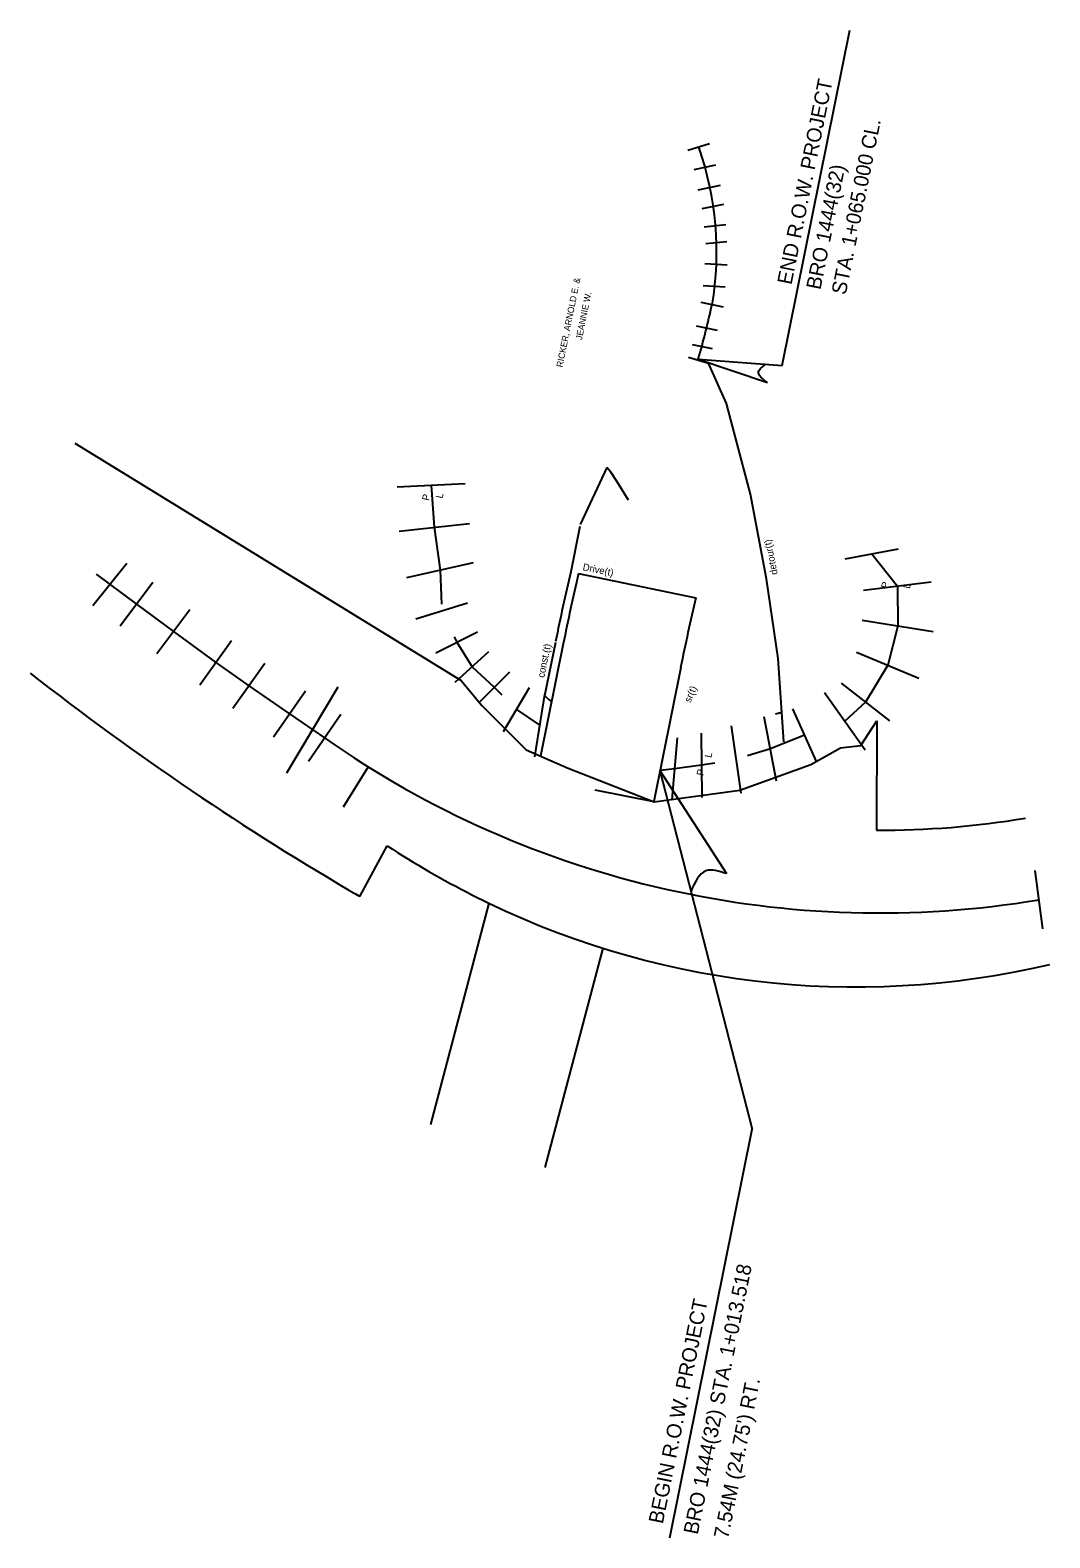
# Model space of a CAD drawing. Extents: x 516033 to 516161, y 162208 to 162397.
import ezdxf

# ---------------------------------------------------------------- set-up
doc = ezdxf.new("R2010")
doc.units = 0
for name, color, linetype in [('Level 1', 7, 'Continuous'), ('Level 10', 7, 'Continuous'), ('Level 19', 7, 'Continuous'), ('Level 3', 7, 'Continuous'), ('Level 4', 7, 'Continuous'), ('Level 6', 7, 'Continuous'), ('Level 60', 7, 'Continuous'), ('Level 7', 7, 'Continuous')]:
    doc.layers.add(name, color=color, linetype=linetype)

msp = doc.modelspace()

# ---------------------------------------------------------------- linework, layer by layer
at = {"layer": 'Level 1'}
for p, q in [((516038.43, 162344.97), (516086.83, 162315.23)), ((516101.53, 162328.62), (516116.23, 162325.59)), ((516099.62, 162319.81), (516096.79, 162305.76)), ((516099.62, 162319.81), (516099.62, 162319.81)), ((516114.33, 162316.85), (516110.95, 162300.06)), ((516086.83, 162315.23), (516089.43, 162312.09)), ((516089.43, 162312.09), (516094.97, 162306.57)), ((516136.88, 162307.11), (516138.92, 162310.2)), ((516138.92, 162310.2), (516138.87, 162296.48)), ((516094.97, 162306.57), (516100.24, 162304.24)), ((516130.62, 162304.7), (516134.35, 162306.8)), ((516134.35, 162306.8), (516136.88, 162307.11)), ((516100.24, 162304.24), (516111.01, 162300.03)), ((516121.72, 162301.49), (516130.62, 162304.7)), ((516111.01, 162300.03), (516121.72, 162301.49)), ((516074.12, 162288.2), (516077.58, 162294.54)), ((516083.04, 162259.63), (516090.36, 162287.33)), ((516097.34, 162254.25), (516104.6, 162281.71))]:
    msp.add_line(p, q, dxfattribs=at)
for centre, radius, start, end in [((516401.07, 162259.12), 307.5, 166.9373, 168.6167), ((516401.07, 162259.12), 292.5, 166.8642, 168.6167), ((516255.76, 162600.89), 361.61, 231.9427, 239.847), ((516139.23, 162407.29), 110.81, 269.8159, 279.4967), ((516137.81, 162386.45), 109.89, 236.7654, 243.1541), ((516136.26, 162382.76), 105.9, 242.9997, 283.2702)]:
    msp.add_arc(centre, radius, start, end, dxfattribs=at)
at = {"layer": 'Level 10'}
for p, q in [((516127.04, 162354.67), (516135.5, 162396.67)), ((516116.52, 162355.46), (516127.04, 162354.67)), ((516116.52, 162355.46), (516125.19, 162352.56)), ((516105.59, 162341.3), (516105.1, 162341.92)), ((516106.37, 162340.09), (516105.59, 162341.3)), ((516107.78, 162337.82), (516106.37, 162340.09)), ((516111.72, 162303.95), (516123.27, 162259.05)), ((516111.72, 162303.95), (516120.06, 162291.05)), ((516112.96, 162207.87), (516123.27, 162259.05))]:
    msp.add_line(p, q, dxfattribs=at)
for points in [[(516125.19, 162352.56), (516124.08, 162353.89), (516125, 162354.84)], [(516120.06, 162291.05), (516117.48, 162291.4), (516115.59, 162288.78)]]:
    msp.add_spline(points, degree=3, dxfattribs=at)
at = {"layer": 'Level 19'}
msp.add_arc((516137.81, 162386.45), 117.09, 236.7654, 237.0475, dxfattribs=at)
at = {"layer": 'Level 3'}
for p, q in [((516083.08, 162339.64), (516083.46, 162334.42)), ((516083.46, 162334.42), (516084.21, 162329.06)), ((516138.28, 162331.09), (516141.47, 162327.05)), ((516084.21, 162329.06), (516084.36, 162324.81)), ((516141.47, 162327.05), (516141.51, 162322.08)), ((516141.51, 162322.08), (516140.26, 162317.17)), ((516085.95, 162320.69), (516086.27, 162320.02)), ((516086.27, 162320.02), (516088.21, 162316.96)), ((516088.21, 162316.96), (516090.98, 162314.39)), ((516140.26, 162317.16), (516137.48, 162312.54)), ((516090.98, 162314.39), (516091.94, 162313.43)), ((516137.48, 162312.54), (516134.89, 162310.12)), ((516093.76, 162311.6), (516096.71, 162309.6)), ((516129.82, 162308.39), (516125.56, 162306.67)), ((516125.56, 162306.67), (516122.7, 162305.79)), ((516113.56, 162304.19), (516111.81, 162303.96)), ((516116.94, 162304.62), (516113.56, 162304.19)), ((516118.6, 162304.9), (516116.94, 162304.62))]:
    msp.add_line(p, q, dxfattribs=at)
at = {"layer": 'Level 6'}
for p, q in [((516115.24, 162381.65), (516117.95, 162382.46)), ((516116, 162379.24), (516118.73, 162379.8)), ((516116.52, 162376.69), (516119.31, 162377.26)), ((516117, 162374.33), (516119.75, 162374.89)), ((516117.29, 162372.06), (516119.98, 162372.33)), ((516117.5, 162369.95), (516120.12, 162370.21)), ((516117.34, 162367.46), (516120.15, 162367.28)), ((516117.16, 162364.69), (516119.9, 162364.51)), ((516116.86, 162362.61), (516119.64, 162362.04)), ((516116.25, 162359.66), (516118.89, 162359.12)), ((516115.77, 162357.3), (516118.28, 162356.79)), ((516115.31, 162355.7), (516117.81, 162354.96)), ((516040.71, 162324.62), (516044.97, 162329.93)), ((516041.13, 162328.55), (516046.17, 162324.8)), ((516044.12, 162322.06), (516048.22, 162327.53)), ((516046.17, 162324.8), (516050.79, 162321.36)), ((516048.73, 162318.61), (516052.85, 162324.11)), ((516050.79, 162321.36), (516056.09, 162317.49)), ((516054.1, 162314.71), (516058.08, 162320.26)), ((516056.09, 162317.49), (516060.24, 162314.58)), ((516058.22, 162311.76), (516062.26, 162317.4)), ((516060.24, 162314.58), (516065.32, 162311.07)), ((516063.32, 162308.19), (516067.32, 162313.95)), ((516071.4, 162314.4), (516064.97, 162303.61)), ((516065.32, 162311.07), (516069.71, 162308.05)), ((516067.7, 162305.15), (516071.77, 162311.01)), ((516075.18, 162304.43), (516072.04, 162299.39)), ((516159.69, 162284.12), (516158.75, 162291.45))]:
    msp.add_line(p, q, dxfattribs=at)
for centre, radius, start, end in [((516078.71, 162368.85), 40.12, 350.5878, 19.2232), ((516005.8, 162386.84), 115.1, 344.1759, 347.7005), ((516139.23, 162407.29), 121.17, 234.989, 279.4967)]:
    msp.add_arc(centre, radius, start, end, dxfattribs=at)
at = {"layer": 'Level 60'}
for p, q in [((516087.33, 162339.84), (516078.82, 162339.43)), ((516079.05, 162333.95), (516087.86, 162334.89)), ((516134.95, 162330.47), (516141.61, 162331.71)), ((516080.03, 162328.14), (516088.39, 162329.99)), ((516137.24, 162326.53), (516145.69, 162327.58)), ((516081.16, 162322.97), (516087.62, 162324.94)), ((516083.68, 162318.7), (516088.87, 162321.33)), ((516137.07, 162322.8), (516145.94, 162321.36)), ((516086.1, 162315.03), (516090.31, 162318.88)), ((516136.35, 162318.79), (516144.16, 162315.53)), ((516089.04, 162312.44), (516092.91, 162316.33)), ((516092.15, 162308.84), (516095.38, 162314.36)), ((516132.36, 162313.71), (516137.43, 162306.54)), ((516134.45, 162314.9), (516140.5, 162310.18)), ((516096.08, 162305.69), (516097.33, 162313.5)), ((516126.32, 162302.64), (516124.79, 162310.7)), ((516128.32, 162311.69), (516131.31, 162305.09)), ((516113.91, 162308.05), (516113.22, 162300.33)), ((516116.9, 162308.65), (516116.97, 162300.6)), ((516120.65, 162309.57), (516121.88, 162301.12)), ((516103.59, 162301.54), (516110.95, 162300.06))]:
    msp.add_line(p, q, dxfattribs=at)
at = {"layer": 'Level 7'}
for p, q in [((516117.83, 162354.99), (516116.53, 162355.46)), ((516105.1, 162341.92), (516101.75, 162334.76)), ((516101.68, 162334.53), (516100.55, 162328.83)), ((516098.64, 162319.98), (516097.29, 162313.3)), ((516097.29, 162313.3), (516097.4, 162313.22)), ((516097.4, 162313.22), (516097.86, 162312.82)), ((516097.86, 162312.82), (516098.17, 162312.56)), ((516127.01, 162311.21), (516126.22, 162311.02))]:
    msp.add_line(p, q, dxfattribs=at)
msp.add_lwpolyline([(516127.27, 162307.54), (516126.53, 162317.97), (516125.1, 162327.97), (516123.06, 162338.56), (516120.08, 162349.93), (516117.83, 162354.99)], dxfattribs=at)
msp.add_arc((516401.07, 162259.12), 308.5, 166.9373, 168.5946, dxfattribs=at)

# ---------------------------------------------------------------- texts
at = {"layer": 'Level 10'}
for s, p in [('END R.O.W. PROJECT', (516128.21, 162364.71)), ('STA. 1+065.000 CL.', (516135, 162363.45)), ('BRO 1444(32)', (516131.83, 162364.08)), ('BRO 1444(32) STA. 1+013.518', (516116.46, 162208.2)), ('BEGIN R.O.W. PROJECT', (516112.09, 162209.54)), ("7.54M (24.75') RT.", (516120.26, 162207.68))]:
    msp.add_text(s, height=1.842, rotation=78.6126, dxfattribs=at).set_placement(p)
at = {"layer": 'Level 3'}
for s, p in [('P', (516082.79, 162337.7)), ('L', (516084.5, 162337.98)), ('P', (516140.3, 162326.72)), ('L', (516143.04, 162326.68)), ('L', (516118.17, 162305.5)), ('P', (516117.17, 162303.25))]:
    msp.add_text(s, height=0.889, rotation=78.6126, dxfattribs=at).set_placement(p)
at = {"layer": 'Level 4'}
for s, height, p in [('RICKER, ARNOLD E. &', 0.8001, (516099.53, 162354.4)), ('JEANNIE W.', 0.8, (516101.96, 162357.83))]:
    msp.add_text(s, height=height, rotation=78.6126, dxfattribs=at).set_placement(p)
at = {"layer": 'Level 7'}
for s, rotation, p in [('detour(t)', 101.4106, (516126.49, 162328.56)), ('Drive(t)', 348.6126, (516102, 162329.05)), ('const.(t)', 78.6126, (516097.24, 162315.53)), ('sr(t)', 66.1567, (516115.54, 162312.39))]:
    msp.add_text(s, height=0.889, rotation=rotation, dxfattribs=at).set_placement(p)

doc.saveas('drawing.dxf')
